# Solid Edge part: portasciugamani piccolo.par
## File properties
Last saved by: i.fialdini
Revision: 62
Tipo di contenuto documento: 0
Accuracy: 0.990
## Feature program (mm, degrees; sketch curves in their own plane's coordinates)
body "unnamed Body 1"
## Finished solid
Body 1: solid body, 10 faces, 24 edges, 16 vertices.
  Faces by surface: plane 7, cylinder 3
  Edges by curve: line 18, circle 6
Bounding box of the edges (mm): 45.000 x 386.500 x 2.000, from (200.5, -210, -147) to (245.5, 176.5, -145).
Cylindrical faces by radius (mm): R5 x2, R33.5 x1
Planar faces by outward normal: +x 2, +y 1, +z 1, -x 2, -z 1
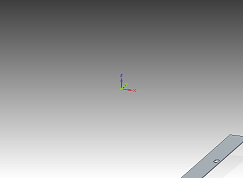
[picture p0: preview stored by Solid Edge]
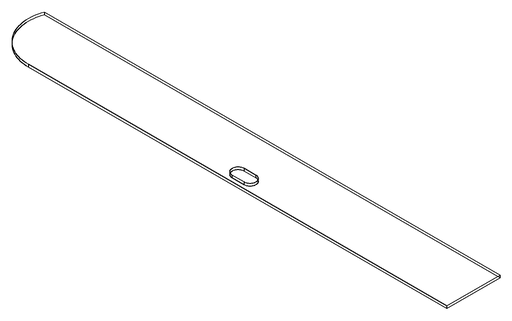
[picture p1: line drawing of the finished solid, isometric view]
